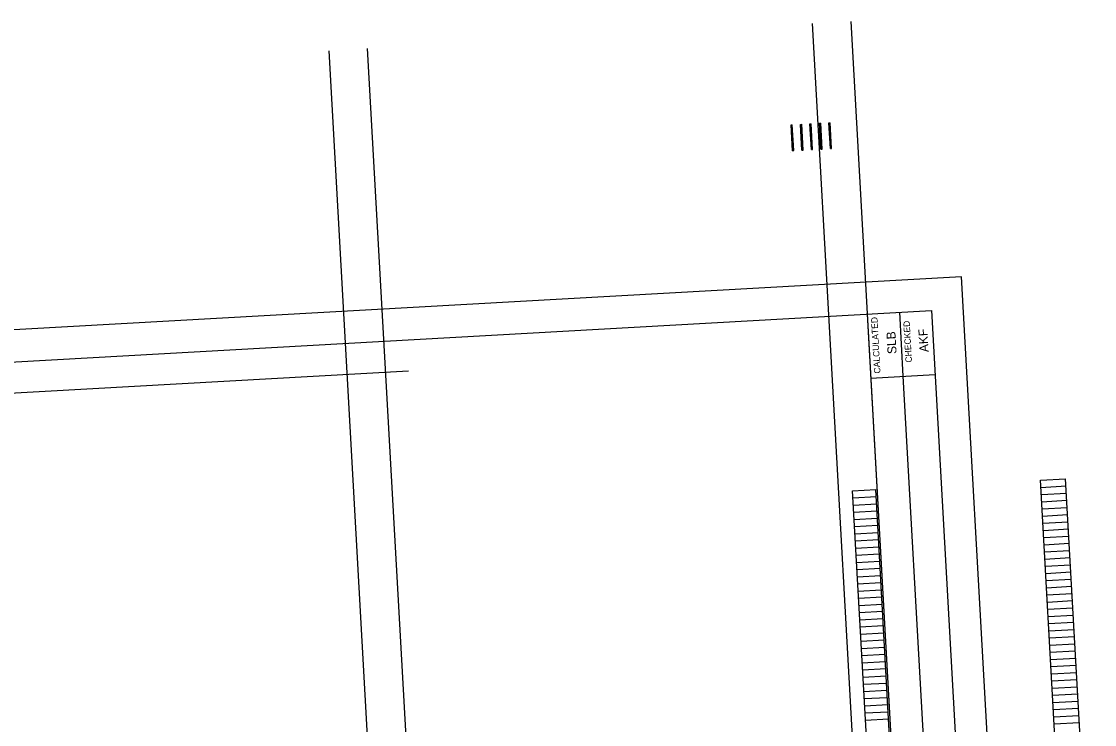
# Model space of a CAD drawing. Extents: x 1822280 to 1825263, y 710141 to 711534.
# Drawn here: x 1823244 to 1824081, y 710986 to 711534 of the extents above; entities that cross this region are included whole.
import ezdxf

# ---------------------------------------------------------------- set-up
doc = ezdxf.new("R2010")
doc.units = 0
for name, color, linetype in [('SC_Scratch1', 7, 'Continuous'), ('SH_Border', 7, 'Continuous'), ('SH_Cut_Line', 7, 'Continuous'), ('SH_Data', 7, 'Continuous')]:
    doc.layers.add(name, color=color, linetype=linetype)

msp = doc.modelspace()

# ---------------------------------------------------------------- linework, layer by layer
at = {"layer": 'SC_Scratch1'}
for p, q in [((1823932.49, 710255.62), (1823860.99, 711532.17)), ((1823962.45, 710257.29), (1823890.94, 711533.85)), ((1823585.26, 710236.17), (1823513.76, 711512.73)), ((1823555.31, 710234.49), (1823483.81, 711511.05)), ((1823545.65, 711261.23), (1822803.55, 711219.67)), ((1823931.48, 711257.13), (1823972.03, 710533.26)), ((1824038.78, 711176.08), (1824058.35, 711177.18)), ((1824080.9, 710774.61), (1824058.35, 711177.18)), ((1823892.21, 711167.87), (1823910.18, 711168.88)), ((1823914.76, 710765.3), (1823892.21, 711167.87)), ((1823932.73, 710766.31), (1823910.18, 711168.88)), ((1824061.33, 710773.51), (1824038.78, 711176.08)), ((1824039.09, 711170.49), (1824058.66, 711171.59)), ((1823892.52, 711162.28), (1823910.49, 711163.29)), ((1824039.41, 711164.9), (1824058.97, 711165.99)), ((1824039.72, 711159.31), (1824059.29, 711160.4)), ((1823892.84, 711156.69), (1823910.81, 711157.69)), ((1823893.15, 711151.1), (1823911.12, 711152.1)), ((1824040.03, 711153.72), (1824059.6, 711154.81)), ((1823893.46, 711145.51), (1823911.43, 711146.51)), ((1824040.34, 711148.12), (1824059.91, 711149.22)), ((1824040.66, 711142.53), (1824060.23, 711143.63)), ((1823893.77, 711139.91), (1823911.75, 711140.92)), ((1823894.09, 711134.32), (1823912.06, 711135.33)), ((1824040.97, 711136.94), (1824060.54, 711138.04)), ((1823894.4, 711128.73), (1823912.37, 711129.74)), ((1824041.28, 711131.35), (1824060.85, 711132.45)), ((1824041.6, 711125.76), (1824061.17, 711126.86)), ((1823894.71, 711123.14), (1823912.69, 711124.15)), ((1823895.03, 711117.55), (1823913, 711118.56)), ((1824041.91, 711120.17), (1824061.48, 711121.26)), ((1823895.34, 711111.96), (1823913.31, 711112.96)), ((1824042.22, 711114.58), (1824061.79, 711115.67)), ((1824042.54, 711108.99), (1824062.11, 711110.08)), ((1823895.65, 711106.37), (1823913.63, 711107.37)), ((1823895.97, 711100.78), (1823913.94, 711101.78)), ((1824042.85, 711103.39), (1824062.42, 711104.49)), ((1823896.28, 711095.18), (1823914.25, 711096.19)), ((1824043.16, 711097.8), (1824062.73, 711098.9)), ((1824043.48, 711092.21), (1824063.05, 711093.31)), ((1823896.59, 711089.59), (1823914.57, 711090.6)), ((1823896.91, 711084), (1823914.88, 711085.01)), ((1824043.79, 711086.62), (1824063.36, 711087.72)), ((1823897.22, 711078.41), (1823915.19, 711079.42)), ((1824044.1, 711081.03), (1824063.67, 711082.13)), ((1824044.42, 711075.44), (1824063.99, 711076.53)), ((1823897.53, 711072.82), (1823915.5, 711073.83)), ((1823897.85, 711067.23), (1823915.82, 711068.23)), ((1824044.73, 711069.85), (1824064.3, 711070.94)), ((1823898.16, 711061.64), (1823916.13, 711062.64)), ((1824045.04, 711064.26), (1824064.61, 711065.35)), ((1824045.36, 711058.66), (1824064.93, 711059.76)), ((1823898.47, 711056.05), (1823916.44, 711057.05)), ((1823898.79, 711050.45), (1823916.76, 711051.46)), ((1824045.67, 711053.07), (1824065.24, 711054.17)), ((1823899.1, 711044.86), (1823917.07, 711045.87)), ((1824045.98, 711047.48), (1824065.55, 711048.58)), ((1824046.3, 711041.89), (1824065.86, 711042.99)), ((1823899.41, 711039.27), (1823917.38, 711040.28)), ((1823899.72, 711033.68), (1823917.7, 711034.69)), ((1824046.61, 711036.3), (1824066.18, 711037.4)), ((1823900.04, 711028.09), (1823918.01, 711029.1)), ((1824046.92, 711030.71), (1824066.49, 711031.8)), ((1824047.23, 711025.12), (1824066.8, 711026.21)), ((1823900.35, 711022.5), (1823918.32, 711023.5)), ((1823900.66, 711016.91), (1823918.64, 711017.91)), ((1824047.55, 711019.53), (1824067.12, 711020.62)), ((1823900.98, 711011.32), (1823918.95, 711012.32)), ((1824047.86, 711013.93), (1824067.43, 711015.03)), ((1824048.17, 711008.34), (1824067.74, 711009.44)), ((1823901.29, 711005.72), (1823919.26, 711006.73)), ((1823901.6, 711000.13), (1823919.58, 711001.14)), ((1824048.49, 711002.75), (1824068.06, 711003.85)), ((1823901.92, 710994.54), (1823919.89, 710995.55)), ((1824048.8, 710997.16), (1824068.37, 710998.26)), ((1824049.11, 710991.57), (1824068.68, 710992.67)), ((1823902.23, 710988.95), (1823920.2, 710989.96)), ((1824049.43, 710985.98), (1824069, 710987.07))]:
    msp.add_line(p, q, dxfattribs=at)
at = {"layer": 'SH_Border'}
for p, q in [((1823962.45, 710257.29), (1823903.73, 711305.65)), ((1823928.69, 711307.05), (1823931.48, 711257.13)), ((1823906.52, 711255.73), (1823956.44, 711258.52))]:
    msp.add_line(p, q, dxfattribs=at)
msp.add_lwpolyline([(1822381.11, 711220.37), (1823953.65, 711308.45), (1824012.37, 710260.09), (1822439.83, 710172.01)], close=True, dxfattribs=at)
at = {"layer": 'SH_Cut_Line'}
msp.add_lwpolyline([(1822341.39, 710141.46), (1824038.73, 710236.53), (1823977.21, 711334.81), (1822279.87, 711239.73)], close=True, dxfattribs=at)
at = {"layer": 'SH_Data'}
for p, q in [((1823844.17, 711453.19), (1823845.07, 711453.24)), ((1823845.3, 711433.06), (1823844.17, 711453.19)), ((1823844.19, 711452.91), (1823845.08, 711452.96)), ((1823844.2, 711452.63), (1823845.1, 711452.68)), ((1823846.2, 711433.11), (1823845.07, 711453.24)), ((1823851.5, 711453.6), (1823852.48, 711453.65)), ((1823852.63, 711433.47), (1823851.5, 711453.6)), ((1823851.51, 711453.32), (1823852.49, 711453.37)), ((1823851.53, 711453.04), (1823852.51, 711453.09)), ((1823851.55, 711452.76), (1823852.52, 711452.81)), ((1823851.56, 711452.48), (1823852.54, 711452.53)), ((1823853.6, 711433.52), (1823852.48, 711453.65)), ((1823858.91, 711454.01), (1823859.89, 711454.07)), ((1823860.03, 711433.88), (1823858.91, 711454.01)), ((1823858.92, 711453.73), (1823859.9, 711453.79)), ((1823858.94, 711453.45), (1823859.92, 711453.51)), ((1823858.95, 711453.17), (1823859.93, 711453.23)), ((1823858.97, 711452.89), (1823859.95, 711452.95)), ((1823858.99, 711452.61), (1823859.96, 711452.67)), ((1823861.01, 711433.94), (1823859.89, 711454.07)), ((1823866.32, 711454.43), (1823867.29, 711454.48)), ((1823867.44, 711434.3), (1823866.32, 711454.43)), ((1823866.33, 711454.15), (1823867.31, 711454.2)), ((1823866.35, 711453.87), (1823867.33, 711453.92)), ((1823866.36, 711453.59), (1823867.34, 711453.64)), ((1823866.38, 711453.31), (1823867.36, 711453.36)), ((1823866.39, 711453.03), (1823867.37, 711453.08)), ((1823866.41, 711452.75), (1823867.39, 711452.8)), ((1823866.43, 711452.47), (1823867.4, 711452.52)), ((1823868.42, 711434.35), (1823867.29, 711454.48)), ((1823873.72, 711454.84), (1823874.62, 711454.89)), ((1823874.85, 711434.71), (1823873.72, 711454.84)), ((1823873.74, 711454.56), (1823874.64, 711454.61)), ((1823873.76, 711454.28), (1823874.65, 711454.33)), ((1823873.77, 711454), (1823874.67, 711454.05)), ((1823873.79, 711453.72), (1823874.69, 711453.77)), ((1823873.8, 711453.44), (1823874.7, 711453.49)), ((1823873.82, 711453.16), (1823874.72, 711453.21)), ((1823873.83, 711452.88), (1823874.73, 711452.93)), ((1823873.85, 711452.6), (1823874.75, 711452.65)), ((1823875.75, 711434.76), (1823874.62, 711454.89)), ((1823844.22, 711452.35), (1823845.12, 711452.4)), ((1823844.23, 711452.07), (1823845.13, 711452.12)), ((1823844.25, 711451.79), (1823845.15, 711451.84)), ((1823844.26, 711451.51), (1823845.16, 711451.56)), ((1823844.28, 711451.23), (1823845.18, 711451.28)), ((1823844.3, 711450.95), (1823845.19, 711451)), ((1823844.31, 711450.67), (1823845.21, 711450.72)), ((1823844.33, 711450.39), (1823845.23, 711450.44)), ((1823844.34, 711450.11), (1823845.24, 711450.16)), ((1823844.36, 711449.83), (1823845.26, 711449.88)), ((1823844.37, 711449.55), (1823845.27, 711449.6)), ((1823844.39, 711449.27), (1823845.29, 711449.32)), ((1823844.41, 711448.99), (1823845.3, 711449.04)), ((1823844.42, 711448.71), (1823845.32, 711448.76)), ((1823844.44, 711448.43), (1823845.34, 711448.48)), ((1823844.45, 711448.15), (1823845.35, 711448.2)), ((1823844.47, 711447.87), (1823845.37, 711447.92)), ((1823844.48, 711447.59), (1823845.38, 711447.64)), ((1823844.5, 711447.31), (1823845.4, 711447.36)), ((1823844.51, 711447.03), (1823845.41, 711447.09)), ((1823844.53, 711446.76), (1823845.43, 711446.81)), ((1823844.55, 711446.48), (1823845.44, 711446.53)), ((1823844.56, 711446.2), (1823845.46, 711446.25)), ((1823844.58, 711445.92), (1823845.48, 711445.97)), ((1823844.59, 711445.64), (1823845.49, 711445.69)), ((1823844.61, 711445.36), (1823845.51, 711445.41)), ((1823844.62, 711445.08), (1823845.52, 711445.13)), ((1823844.64, 711444.8), (1823845.54, 711444.85)), ((1823844.66, 711444.52), (1823845.55, 711444.57)), ((1823844.67, 711444.24), (1823845.57, 711444.29)), ((1823851.58, 711452.2), (1823852.56, 711452.25)), ((1823851.59, 711451.92), (1823852.57, 711451.97)), ((1823851.61, 711451.64), (1823852.59, 711451.69)), ((1823851.62, 711451.36), (1823852.6, 711451.41)), ((1823851.64, 711451.08), (1823852.62, 711451.13)), ((1823851.66, 711450.8), (1823852.63, 711450.85)), ((1823851.67, 711450.52), (1823852.65, 711450.58)), ((1823851.69, 711450.24), (1823852.67, 711450.3)), ((1823851.7, 711449.96), (1823852.68, 711450.02)), ((1823851.72, 711449.68), (1823852.7, 711449.74)), ((1823851.73, 711449.4), (1823852.71, 711449.46)), ((1823851.75, 711449.12), (1823852.73, 711449.18)), ((1823851.77, 711448.84), (1823852.74, 711448.9)), ((1823851.78, 711448.56), (1823852.76, 711448.62)), ((1823851.8, 711448.28), (1823852.77, 711448.34)), ((1823851.81, 711448), (1823852.79, 711448.06)), ((1823851.83, 711447.72), (1823852.81, 711447.78)), ((1823851.84, 711447.45), (1823852.82, 711447.5)), ((1823851.86, 711447.17), (1823852.84, 711447.22)), ((1823851.87, 711446.89), (1823852.85, 711446.94)), ((1823851.89, 711446.61), (1823852.87, 711446.66)), ((1823851.91, 711446.33), (1823852.88, 711446.38)), ((1823851.92, 711446.05), (1823852.9, 711446.1)), ((1823851.94, 711445.77), (1823852.92, 711445.82)), ((1823851.95, 711445.49), (1823852.93, 711445.54)), ((1823851.97, 711445.21), (1823852.95, 711445.26)), ((1823851.98, 711444.93), (1823852.96, 711444.98)), ((1823852, 711444.65), (1823852.98, 711444.7)), ((1823852.02, 711444.37), (1823852.99, 711444.43)), ((1823852.03, 711444.09), (1823853.01, 711444.15)), ((1823859, 711452.33), (1823859.98, 711452.39)), ((1823859.02, 711452.05), (1823860, 711452.11)), ((1823859.03, 711451.77), (1823860.01, 711451.83)), ((1823859.05, 711451.49), (1823860.03, 711451.55)), ((1823859.06, 711451.22), (1823860.04, 711451.27)), ((1823859.08, 711450.94), (1823860.06, 711450.99)), ((1823859.1, 711450.66), (1823860.07, 711450.71)), ((1823859.11, 711450.38), (1823860.09, 711450.43)), ((1823859.13, 711450.1), (1823860.11, 711450.15)), ((1823859.14, 711449.82), (1823860.12, 711449.87)), ((1823859.16, 711449.54), (1823860.14, 711449.59)), ((1823859.17, 711449.26), (1823860.15, 711449.31)), ((1823859.19, 711448.98), (1823860.17, 711449.03)), ((1823859.2, 711448.7), (1823860.18, 711448.75)), ((1823859.22, 711448.42), (1823860.2, 711448.47)), ((1823859.24, 711448.14), (1823860.21, 711448.19)), ((1823859.25, 711447.86), (1823860.23, 711447.92)), ((1823859.27, 711447.58), (1823860.25, 711447.64)), ((1823859.28, 711447.3), (1823860.26, 711447.36)), ((1823859.3, 711447.02), (1823860.28, 711447.08)), ((1823859.31, 711446.74), (1823860.29, 711446.8)), ((1823859.33, 711446.46), (1823860.31, 711446.52)), ((1823859.35, 711446.18), (1823860.32, 711446.24)), ((1823859.36, 711445.9), (1823860.34, 711445.96)), ((1823859.38, 711445.62), (1823860.36, 711445.68)), ((1823859.39, 711445.34), (1823860.37, 711445.4)), ((1823859.41, 711445.06), (1823860.39, 711445.12)), ((1823859.42, 711444.79), (1823860.4, 711444.84)), ((1823859.44, 711444.51), (1823860.42, 711444.56)), ((1823859.46, 711444.23), (1823860.43, 711444.28)), ((1823866.44, 711452.19), (1823867.42, 711452.24)), ((1823866.46, 711451.91), (1823867.44, 711451.96)), ((1823866.47, 711451.63), (1823867.45, 711451.68)), ((1823866.49, 711451.35), (1823867.47, 711451.41)), ((1823866.5, 711451.07), (1823867.48, 711451.13)), ((1823866.52, 711450.79), (1823867.5, 711450.85)), ((1823866.53, 711450.51), (1823867.51, 711450.57)), ((1823866.55, 711450.23), (1823867.53, 711450.29)), ((1823866.57, 711449.95), (1823867.54, 711450.01)), ((1823866.58, 711449.67), (1823867.56, 711449.73)), ((1823866.6, 711449.39), (1823867.58, 711449.45)), ((1823866.61, 711449.11), (1823867.59, 711449.17)), ((1823866.63, 711448.83), (1823867.61, 711448.89)), ((1823866.64, 711448.55), (1823867.62, 711448.61)), ((1823866.66, 711448.28), (1823867.64, 711448.33)), ((1823866.68, 711448), (1823867.65, 711448.05)), ((1823866.69, 711447.72), (1823867.67, 711447.77)), ((1823866.71, 711447.44), (1823867.69, 711447.49)), ((1823866.72, 711447.16), (1823867.7, 711447.21)), ((1823866.74, 711446.88), (1823867.72, 711446.93)), ((1823866.75, 711446.6), (1823867.73, 711446.65)), ((1823866.77, 711446.32), (1823867.75, 711446.37)), ((1823866.79, 711446.04), (1823867.76, 711446.09)), ((1823866.8, 711445.76), (1823867.78, 711445.81)), ((1823866.82, 711445.48), (1823867.8, 711445.53)), ((1823866.83, 711445.2), (1823867.81, 711445.25)), ((1823866.85, 711444.92), (1823867.83, 711444.98)), ((1823866.86, 711444.64), (1823867.84, 711444.7)), ((1823866.88, 711444.36), (1823867.86, 711444.42)), ((1823866.9, 711444.08), (1823867.87, 711444.14)), ((1823873.87, 711452.32), (1823874.76, 711452.37)), ((1823873.88, 711452.05), (1823874.78, 711452.1)), ((1823873.9, 711451.77), (1823874.79, 711451.82)), ((1823873.91, 711451.49), (1823874.81, 711451.54)), ((1823873.93, 711451.21), (1823874.83, 711451.26)), ((1823873.94, 711450.93), (1823874.84, 711450.98)), ((1823873.96, 711450.65), (1823874.86, 711450.7)), ((1823873.97, 711450.37), (1823874.87, 711450.42)), ((1823873.99, 711450.09), (1823874.89, 711450.14)), ((1823874.01, 711449.81), (1823874.9, 711449.86)), ((1823874.02, 711449.53), (1823874.92, 711449.58)), ((1823874.04, 711449.25), (1823874.94, 711449.3)), ((1823874.05, 711448.97), (1823874.95, 711449.02)), ((1823874.07, 711448.69), (1823874.97, 711448.74)), ((1823874.08, 711448.41), (1823874.98, 711448.46)), ((1823874.1, 711448.13), (1823875, 711448.18)), ((1823874.12, 711447.85), (1823875.01, 711447.9)), ((1823874.13, 711447.57), (1823875.03, 711447.62)), ((1823874.15, 711447.29), (1823875.05, 711447.34)), ((1823874.16, 711447.01), (1823875.06, 711447.06)), ((1823874.18, 711446.73), (1823875.08, 711446.78)), ((1823874.19, 711446.45), (1823875.09, 711446.5)), ((1823874.21, 711446.17), (1823875.11, 711446.22)), ((1823874.23, 711445.89), (1823875.12, 711445.94)), ((1823874.24, 711445.62), (1823875.14, 711445.67)), ((1823874.26, 711445.34), (1823875.16, 711445.39)), ((1823874.27, 711445.06), (1823875.17, 711445.11)), ((1823874.29, 711444.78), (1823875.19, 711444.83)), ((1823874.3, 711444.5), (1823875.2, 711444.55)), ((1823874.32, 711444.22), (1823875.22, 711444.27)), ((1823844.69, 711443.96), (1823845.59, 711444.01)), ((1823844.7, 711443.68), (1823845.6, 711443.73)), ((1823844.72, 711443.4), (1823845.62, 711443.45)), ((1823844.73, 711443.12), (1823845.63, 711443.17)), ((1823844.75, 711442.84), (1823845.65, 711442.89)), ((1823844.77, 711442.56), (1823845.66, 711442.61)), ((1823844.78, 711442.28), (1823845.68, 711442.33)), ((1823844.8, 711442), (1823845.7, 711442.05)), ((1823844.81, 711441.72), (1823845.71, 711441.77)), ((1823844.83, 711441.44), (1823845.73, 711441.49)), ((1823844.84, 711441.16), (1823845.74, 711441.21)), ((1823844.86, 711440.88), (1823845.76, 711440.93)), ((1823844.88, 711440.6), (1823845.77, 711440.66)), ((1823844.89, 711440.33), (1823845.79, 711440.38)), ((1823844.91, 711440.05), (1823845.81, 711440.1)), ((1823844.92, 711439.77), (1823845.82, 711439.82)), ((1823844.94, 711439.49), (1823845.84, 711439.54)), ((1823844.95, 711439.21), (1823845.85, 711439.26)), ((1823844.97, 711438.93), (1823845.87, 711438.98)), ((1823844.98, 711438.65), (1823845.88, 711438.7)), ((1823845, 711438.37), (1823845.9, 711438.42)), ((1823845.02, 711438.09), (1823845.91, 711438.14)), ((1823845.03, 711437.81), (1823845.93, 711437.86)), ((1823845.05, 711437.53), (1823845.95, 711437.58)), ((1823845.06, 711437.25), (1823845.96, 711437.3)), ((1823845.08, 711436.97), (1823845.98, 711437.02)), ((1823845.09, 711436.69), (1823845.99, 711436.74)), ((1823845.11, 711436.41), (1823846.01, 711436.46)), ((1823845.13, 711436.13), (1823846.02, 711436.18)), ((1823845.14, 711435.85), (1823846.04, 711435.9)), ((1823852.05, 711443.81), (1823853.03, 711443.87)), ((1823852.06, 711443.53), (1823853.04, 711443.59)), ((1823852.08, 711443.25), (1823853.06, 711443.31)), ((1823852.09, 711442.97), (1823853.07, 711443.03)), ((1823852.11, 711442.69), (1823853.09, 711442.75)), ((1823852.13, 711442.41), (1823853.1, 711442.47)), ((1823852.14, 711442.13), (1823853.12, 711442.19)), ((1823852.16, 711441.85), (1823853.14, 711441.91)), ((1823852.17, 711441.57), (1823853.15, 711441.63)), ((1823852.19, 711441.3), (1823853.17, 711441.35)), ((1823852.2, 711441.02), (1823853.18, 711441.07)), ((1823852.22, 711440.74), (1823853.2, 711440.79)), ((1823852.23, 711440.46), (1823853.21, 711440.51)), ((1823852.25, 711440.18), (1823853.23, 711440.23)), ((1823852.27, 711439.9), (1823853.24, 711439.95)), ((1823852.28, 711439.62), (1823853.26, 711439.67)), ((1823852.3, 711439.34), (1823853.28, 711439.39)), ((1823852.31, 711439.06), (1823853.29, 711439.11)), ((1823852.33, 711438.78), (1823853.31, 711438.83)), ((1823852.34, 711438.5), (1823853.32, 711438.55)), ((1823852.36, 711438.22), (1823853.34, 711438.27)), ((1823852.38, 711437.94), (1823853.35, 711438)), ((1823852.39, 711437.66), (1823853.37, 711437.72)), ((1823852.41, 711437.38), (1823853.39, 711437.44)), ((1823852.42, 711437.1), (1823853.4, 711437.16)), ((1823852.44, 711436.82), (1823853.42, 711436.88)), ((1823852.45, 711436.54), (1823853.43, 711436.6)), ((1823852.47, 711436.26), (1823853.45, 711436.32)), ((1823852.49, 711435.98), (1823853.46, 711436.04)), ((1823852.5, 711435.7), (1823853.48, 711435.76)), ((1823859.47, 711443.95), (1823860.45, 711444)), ((1823859.49, 711443.67), (1823860.47, 711443.72)), ((1823859.5, 711443.39), (1823860.48, 711443.44)), ((1823859.52, 711443.11), (1823860.5, 711443.16)), ((1823859.53, 711442.83), (1823860.51, 711442.88)), ((1823859.55, 711442.55), (1823860.53, 711442.6)), ((1823859.57, 711442.27), (1823860.54, 711442.32)), ((1823859.58, 711441.99), (1823860.56, 711442.04)), ((1823859.6, 711441.71), (1823860.57, 711441.76)), ((1823859.61, 711441.43), (1823860.59, 711441.49)), ((1823859.63, 711441.15), (1823860.61, 711441.21)), ((1823859.64, 711440.87), (1823860.62, 711440.93)), ((1823859.66, 711440.59), (1823860.64, 711440.65)), ((1823859.67, 711440.31), (1823860.65, 711440.37)), ((1823859.69, 711440.03), (1823860.67, 711440.09)), ((1823859.71, 711439.75), (1823860.68, 711439.81)), ((1823859.72, 711439.47), (1823860.7, 711439.53)), ((1823859.74, 711439.19), (1823860.72, 711439.25)), ((1823859.75, 711438.91), (1823860.73, 711438.97)), ((1823859.77, 711438.63), (1823860.75, 711438.69)), ((1823859.78, 711438.36), (1823860.76, 711438.41)), ((1823859.8, 711438.08), (1823860.78, 711438.13)), ((1823859.82, 711437.8), (1823860.79, 711437.85)), ((1823859.83, 711437.52), (1823860.81, 711437.57)), ((1823859.85, 711437.24), (1823860.83, 711437.29)), ((1823859.86, 711436.96), (1823860.84, 711437.01)), ((1823859.88, 711436.68), (1823860.86, 711436.73)), ((1823859.89, 711436.4), (1823860.87, 711436.45)), ((1823859.91, 711436.12), (1823860.89, 711436.17)), ((1823859.93, 711435.84), (1823860.9, 711435.89)), ((1823866.91, 711443.8), (1823867.89, 711443.86)), ((1823866.93, 711443.52), (1823867.9, 711443.58)), ((1823866.94, 711443.24), (1823867.92, 711443.3)), ((1823866.96, 711442.96), (1823867.94, 711443.02)), ((1823866.97, 711442.68), (1823867.95, 711442.74)), ((1823866.99, 711442.4), (1823867.97, 711442.46)), ((1823867, 711442.12), (1823867.98, 711442.18)), ((1823867.02, 711441.85), (1823868, 711441.9)), ((1823867.04, 711441.57), (1823868.01, 711441.62)), ((1823867.05, 711441.29), (1823868.03, 711441.34)), ((1823867.07, 711441.01), (1823868.05, 711441.06)), ((1823867.08, 711440.73), (1823868.06, 711440.78)), ((1823867.1, 711440.45), (1823868.08, 711440.5)), ((1823867.11, 711440.17), (1823868.09, 711440.22)), ((1823867.13, 711439.89), (1823868.11, 711439.94)), ((1823867.15, 711439.61), (1823868.12, 711439.66)), ((1823867.16, 711439.33), (1823868.14, 711439.38)), ((1823867.18, 711439.05), (1823868.16, 711439.1)), ((1823867.19, 711438.77), (1823868.17, 711438.83)), ((1823867.21, 711438.49), (1823868.19, 711438.55)), ((1823867.22, 711438.21), (1823868.2, 711438.27)), ((1823867.24, 711437.93), (1823868.22, 711437.99)), ((1823867.26, 711437.65), (1823868.23, 711437.71)), ((1823867.27, 711437.37), (1823868.25, 711437.43)), ((1823867.29, 711437.09), (1823868.27, 711437.15)), ((1823867.3, 711436.81), (1823868.28, 711436.87)), ((1823867.32, 711436.53), (1823868.3, 711436.59)), ((1823867.33, 711436.25), (1823868.31, 711436.31)), ((1823867.35, 711435.97), (1823868.33, 711436.03)), ((1823867.36, 711435.7), (1823868.34, 711435.75)), ((1823874.33, 711443.94), (1823875.23, 711443.99)), ((1823874.35, 711443.66), (1823875.25, 711443.71)), ((1823874.37, 711443.38), (1823875.26, 711443.43)), ((1823874.38, 711443.1), (1823875.28, 711443.15)), ((1823874.4, 711442.82), (1823875.3, 711442.87)), ((1823874.41, 711442.54), (1823875.31, 711442.59)), ((1823874.43, 711442.26), (1823875.33, 711442.31)), ((1823874.44, 711441.98), (1823875.34, 711442.03)), ((1823874.46, 711441.7), (1823875.36, 711441.75)), ((1823874.48, 711441.42), (1823875.37, 711441.47)), ((1823874.49, 711441.14), (1823875.39, 711441.19)), ((1823874.51, 711440.86), (1823875.41, 711440.91)), ((1823874.52, 711440.58), (1823875.42, 711440.63)), ((1823874.54, 711440.3), (1823875.44, 711440.35)), ((1823874.55, 711440.02), (1823875.45, 711440.07)), ((1823874.57, 711439.74), (1823875.47, 711439.79)), ((1823874.59, 711439.46), (1823875.48, 711439.52)), ((1823874.6, 711439.19), (1823875.5, 711439.24)), ((1823874.62, 711438.91), (1823875.52, 711438.96)), ((1823874.63, 711438.63), (1823875.53, 711438.68)), ((1823874.65, 711438.35), (1823875.55, 711438.4)), ((1823874.66, 711438.07), (1823875.56, 711438.12)), ((1823874.68, 711437.79), (1823875.58, 711437.84)), ((1823874.7, 711437.51), (1823875.59, 711437.56)), ((1823874.71, 711437.23), (1823875.61, 711437.28)), ((1823874.73, 711436.95), (1823875.62, 711437)), ((1823874.74, 711436.67), (1823875.64, 711436.72)), ((1823874.76, 711436.39), (1823875.66, 711436.44)), ((1823874.77, 711436.11), (1823875.67, 711436.16)), ((1823874.79, 711435.83), (1823875.69, 711435.88)), ((1823843.36, 711431.97), (1823843.36, 711431.97)), ((1823845.16, 711435.57), (1823846.06, 711435.62)), ((1823845.17, 711435.29), (1823846.07, 711435.34)), ((1823845.19, 711435.01), (1823846.09, 711435.06)), ((1823845.2, 711434.73), (1823846.1, 711434.78)), ((1823845.22, 711434.45), (1823846.12, 711434.5)), ((1823845.24, 711434.18), (1823846.13, 711434.23)), ((1823845.25, 711433.9), (1823846.15, 711433.95)), ((1823845.27, 711433.62), (1823846.17, 711433.67)), ((1823845.28, 711433.34), (1823846.18, 711433.39)), ((1823845.3, 711433.06), (1823846.2, 711433.11)), ((1823852.52, 711435.42), (1823853.5, 711435.48)), ((1823852.53, 711435.14), (1823853.51, 711435.2)), ((1823852.55, 711434.87), (1823853.53, 711434.92)), ((1823852.56, 711434.59), (1823853.54, 711434.64)), ((1823852.58, 711434.31), (1823853.56, 711434.36)), ((1823852.6, 711434.03), (1823853.57, 711434.08)), ((1823852.61, 711433.75), (1823853.59, 711433.8)), ((1823852.63, 711433.47), (1823853.6, 711433.52)), ((1823859.94, 711435.56), (1823860.92, 711435.61)), ((1823859.96, 711435.28), (1823860.93, 711435.33)), ((1823859.97, 711435), (1823860.95, 711435.06)), ((1823859.99, 711434.72), (1823860.97, 711434.78)), ((1823860, 711434.44), (1823860.98, 711434.5)), ((1823860.02, 711434.16), (1823861, 711434.22)), ((1823860.03, 711433.88), (1823861.01, 711433.94)), ((1823867.38, 711435.42), (1823868.36, 711435.47)), ((1823867.4, 711435.14), (1823868.37, 711435.19)), ((1823867.41, 711434.86), (1823868.39, 711434.91)), ((1823867.43, 711434.58), (1823868.41, 711434.63)), ((1823867.44, 711434.3), (1823868.42, 711434.35)), ((1823874.8, 711435.55), (1823875.7, 711435.6)), ((1823874.82, 711435.27), (1823875.72, 711435.32)), ((1823874.84, 711434.99), (1823875.73, 711435.04)), ((1823874.85, 711434.71), (1823875.75, 711434.76))]:
    msp.add_line(p, q, dxfattribs=at)

# ---------------------------------------------------------------- texts
for s, height, p in [('CALCULATED', 5, (1823913.95, 711259.38)), ('CHECKED', 5, (1823938.51, 711267.93)), ('AKF', 7, (1823951.45, 711276.13)), ('SLB', 7, (1823926.49, 711274.68))]:
    msp.add_text(s, height=height, rotation=93.20591, dxfattribs=at).set_placement(p)

doc.saveas('drawing.dxf')
